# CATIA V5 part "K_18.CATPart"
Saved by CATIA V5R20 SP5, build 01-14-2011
Part number: 18
Bounding box of the stored display mesh (mm): x 0 to 70, y -20 to 30, z -20 to 20
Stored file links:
  G:\Khaled_CFAO_2011\ST2M\ST2M_GR1\lpierredon\Khaled\CAD_thinkMOTION\K_18.CATPart
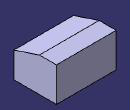
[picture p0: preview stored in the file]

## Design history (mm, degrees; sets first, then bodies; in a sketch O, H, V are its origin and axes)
Body1 (main body)
  Sketch1 on yz-plane, origin (0, 0, 0), H (0, 1, 0), V (0, 0, 1)
    line L1 (-20, -20) -> (30, -20)
    line L2 (30, -20) -> (30, 20)
    line L3 (30, 20) -> (10, 20)
    line L4 (10, 20) -> (-20, 10)
    line L5 (-20, 10) -> (-20, -20)
    length L2 = 40
    length L1 = 50
    length L3 = 20
    length L5 = 30
    horizontal: L1 H, L3 H
    vertical: L2 V, L5 V
  Pad1: profile Sketch1, direction (1, 0, 0), length 70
